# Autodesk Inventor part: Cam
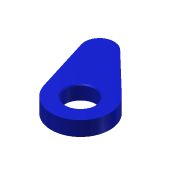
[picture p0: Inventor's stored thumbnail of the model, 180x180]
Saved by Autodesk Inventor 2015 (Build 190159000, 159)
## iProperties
Created: 2019-10
Part Number: Cam
Material: 一般
Document SubType Name: Modeling
Designer: Kuan_Lun Hsu
Density: 1 g/cm^3
Appearance: 藍色 - 牆面油漆 - 亮面
Mass: 460.643 g
Surface Area: 518.93 cm^2
Volume: 460.643 cm^3
Author: Kuan_Lun Hsu
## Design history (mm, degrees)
sketch "草圖1" dims "d4" = 60
  geometry: L1 (0, 220)-(200, 220); L2 (200, 220)-(200, 180); L3 (200, 180)-(0, 180); L4 (0, 180)-(0, 220); L5 (-21.213, 21.213)-(21.213, -21.213); L6 (21.213, -21.213)-(289.914, 247.487); L7 (289.914, 247.487)-(247.487, 289.914); L8 (247.487, 289.914)-(-21.213, 21.213); L9 (0, 0)-(200, 200); L10 (141.421, 141.421)-(247.487, 247.487); L11 (134.35, 148.492)-(240.416, 254.558); L12 (254.558, 240.416)-(148.492, 134.35); L13 (236.961, 152.108)-(300, 50); L14 (208.305, 143.231)-(242.687, 32.245); L15 (257.738, 173.749)-(341.553, 93.282); L16 (-60, 180)-(390, 180); L17 (390, 180)-(390, -70); L18 (390, -70)-(-60, -70); L19 (-60, -70)-(-60, 180); C1 r 10 at (200, 200); C2 r 15 at (0, 0); C3 r 30 at (300, 50); A1 r 10 centre (141.421, 141.421) between (134.35, 148.492) and (148.492, 134.35); A2 r 10 centre (247.487, 247.487) between (254.558, 240.416) and (240.416, 254.558); A3 r 60 centre (300, 50) between (242.687, 32.245) and (341.553, 93.282); A4 r 30 centre (236.961, 152.108) between (208.305, 143.231) and (257.738, 173.749); 4 further points
  constraints: 40 end point, 9 parallel, 9 tangent, 8 point on circle, 7 centre point, 4 coincident, 4 midpoint, 3 perpendicular, 2 horizontal, 2 vertical alignment, 1 collinear, 1 equal radius, 1 point on line, 5 other
  dimensions: "d0" = 40 distance between parallel lines of L3 L1; "d1" = 200 distance of L1.start L1.end; "d2" = 180 distance from line of point (0, 0) L3; "d3" = 20 diameter of C1; "d5" = 380 distance of L5.end L6.end; "d6" = 30 distance from line of L7 L10.end; "d7" = 150 distance of L11.start L11.end; "d8" = 60 diameter of A4; "d9" = 120 diameter of A3; "d10" = 120 distance of L13.start L13.end; "d11" = 300 horizontal distance of L13.end point (0, 0); "d12" = 50 vertical distance of point (0, 0) L13.end; "d13" = 60 distance between parallel lines of L19 L4; "d14" = 250 distance of L18.end L16.start; "d15" = 450 distance of L17.end L18.end; "d16" = 45 deg angle of L6 L18 (derived); "d17" = 30 diameter of C2; "d18" = 60 diameter of C3
extrude "擠出1" new body sketch "草圖1" distance "d19" = 30; taper "d20" = 0 deg
chamfer "倒角1" distance "d21" = 2; stored, may be unused: second distance "d22" = 2, angle "d23" = 45 deg
node "實體1"
